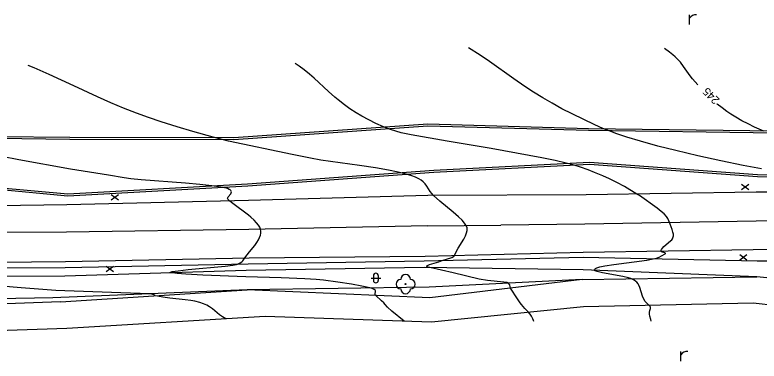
# Model space of a CAD drawing. Extents: x -593772 to -592667, y -1183541 to -1183371.
# Drawn here: x -592923.7 to -592846.1, y -1183541.5 to -1183505.4 of the extents above; entities that cross this region are included whole.
import ezdxf

# ---------------------------------------------------------------- set-up
doc = ezdxf.new("R2010")
doc.units = 0
for name, color, linetype in [('bez obruby', 7, 'Continuous'), ('hlavni vrstevnice', 7, 'Continuous'), ('popis ploch', 7, 'Continuous'), ('rozhrani ploch', 7, 'Continuous'), ('svisle dopravni znaceni', 7, 'Continuous'), ('terenni hrany', 7, 'Continuous'), ('vodorovne dopravni znaceni', 7, 'Continuous'), ('vrstevnice', 7, 'Continuous'), ('zelen', 7, 'Continuous')]:
    doc.layers.add(name, color=color, linetype=linetype)

msp = doc.modelspace()

# ---------------------------------------------------------------- linework, layer by layer
at = {"layer": 'bez obruby'}
for p, q in [((-592880.6, -1183524.23), (-592899.31, -1183524.75)), ((-592864.09, -1183524.15), (-592880.6, -1183524.23)), ((-592846.36, -1183523.87), (-592864.09, -1183524.15)), ((-592829.77, -1183523.8), (-592846.36, -1183523.87)), ((-592899.31, -1183524.75), (-592918.25, -1183525.18)), ((-592918.25, -1183525.18), (-592936.03, -1183525.44)), ((-592829.73, -1183529.64), (-592846.7, -1183529.89)), ((-592880.9, -1183530.57), (-592899.23, -1183530.75)), ((-592864.41, -1183530.16), (-592880.9, -1183530.57)), ((-592846.7, -1183529.89), (-592864.41, -1183530.16)), ((-592918.4, -1183531.12), (-592935.82, -1183531.3)), ((-592899.23, -1183530.75), (-592918.4, -1183531.12))]:
    msp.add_line(p, q, dxfattribs=at)
at = {"layer": 'hlavni vrstevnice'}
for points in [[(-592852.443, -1183512.671), (-592853.013, -1183512.029), (-592853.258, -1183511.72), (-592853.941, -1183510.749), (-592854.277, -1183510.319), (-592854.546, -1183510.018), (-592854.802, -1183509.762), (-592855.068, -1183509.524), (-592855.422, -1183509.244), (-592855.932, -1183508.889)], [(-592845.577, -1183517.486), (-592846.527, -1183517.076), (-592847.221, -1183516.746), (-592847.868, -1183516.408), (-592848.487, -1183516.054), (-592849.002, -1183515.733), (-592849.424, -1183515.451), (-592849.931, -1183515.08), (-592850.433, -1183514.679), (-592850.446, -1183514.668)], [(-592901.692, -1183537.077), (-592902.039, -1183536.871), (-592902.341, -1183536.655), (-592903.078, -1183536.043), (-592903.383, -1183535.831), (-592903.674, -1183535.666), (-592904.017, -1183535.507), (-592904.404, -1183535.365), (-592904.903, -1183535.226), (-592905.34, -1183535.149), (-592905.926, -1183535.082), (-592907.518, -1183534.928), (-592908.263, -1183534.829), (-592908.8, -1183534.726), (-592909.032, -1183534.664), (-592909.098, -1183534.629), (-592909.172, -1183534.563), (-592909.298, -1183534.524), (-592909.619, -1183534.487), (-592912.638, -1183534.364), (-592918.473, -1183534.167), (-592919.418, -1183534.12), (-592923.011, -1183533.839), (-592927.175, -1183533.483)]]:
    msp.add_lwpolyline(points, dxfattribs=at)
at = {"layer": 'popis ploch'}
for p, q in [((-592853.33, -1183506.38), (-592853.33, -1183505.38)), ((-592886.53, -1183532.82), (-592885.53, -1183532.82)), ((-592886.28, -1183532.57), (-592886.28, -1183533.07)), ((-592885.78, -1183532.57), (-592885.78, -1183533.07)), ((-592854.24, -1183541.49), (-592854.24, -1183540.49))]:
    msp.add_line(p, q, dxfattribs=at)
for centre, radius, start, end in [((-592852.693, -1183506.117), 0.746, 81.32683, 148.70696), ((-592886.031, -1183532.57), 0.25, 0, 180), ((-592886.031, -1183533.07), 0.25, 180, 0), ((-592853.603, -1183541.228), 0.746, 81.32683, 148.70696)]:
    msp.add_arc(centre, radius, start, end, dxfattribs=at)
at = {"layer": 'rozhrani ploch'}
for p, q in [((-592864.53, -1183532.96), (-592880.42, -1183534.89)), ((-592918.93, -1183535.32), (-592899.45, -1183534.04)), ((-592880.42, -1183534.89), (-592899.45, -1183534.04)), ((-592918.93, -1183535.32), (-592936.14, -1183535.94)), ((-592864.36, -1183535.82), (-592880.22, -1183537.41)), ((-592846.7, -1183535.46), (-592864.36, -1183535.82)), ((-592830.25, -1183537.2), (-592846.7, -1183535.46)), ((-592897.56, -1183536.83), (-592918.27, -1183538.07)), ((-592880.22, -1183537.41), (-592897.56, -1183536.83)), ((-592918.27, -1183538.07), (-592936.46, -1183538.75))]:
    msp.add_line(p, q, dxfattribs=at)
at = {"layer": 'svisle dopravni znaceni'}
for p, q in [((-592847.895, -1183523.591), (-592847.145, -1183523.029)), ((-592847.895, -1183523.029), (-592847.145, -1183523.591)), ((-592913.635, -1183524.681), (-592912.885, -1183524.119)), ((-592913.635, -1183524.119), (-592912.885, -1183524.681)), ((-592848.085, -1183530.931), (-592847.335, -1183530.369)), ((-592848.085, -1183530.369), (-592847.335, -1183530.931)), ((-592914.145, -1183532.131), (-592913.395, -1183531.569)), ((-592914.145, -1183531.569), (-592913.395, -1183532.131))]:
    msp.add_line(p, q, dxfattribs=at)
at = {"layer": 'terenni hrany'}
for p, q in [((-592900.86, -1183518.18), (-592880.6, -1183516.75)), ((-592880.6, -1183516.75), (-592863.86, -1183517.21)), ((-592863.86, -1183517.21), (-592843.44, -1183517.49)), ((-592934.32, -1183517.95), (-592917.94, -1183518.13)), ((-592917.94, -1183518.13), (-592900.86, -1183518.18)), ((-592863.75, -1183520.98), (-592879.99, -1183521.8)), ((-592846.23, -1183522.25), (-592863.75, -1183520.98)), ((-592879.99, -1183521.8), (-592899.4, -1183523.24)), ((-592918.15, -1183524.28), (-592935.47, -1183522.68)), ((-592829.92, -1183522.84), (-592846.23, -1183522.25)), ((-592899.4, -1183523.24), (-592918.15, -1183524.28)), ((-592899.36, -1183531.38), (-592918.42, -1183531.76)), ((-592880.99, -1183531.05), (-592899.36, -1183531.38)), ((-592864.41, -1183530.67), (-592880.99, -1183531.05)), ((-592846.26, -1183531.07), (-592864.41, -1183530.67)), ((-592829.79, -1183530.96), (-592846.26, -1183531.07)), ((-592918.42, -1183531.76), (-592935.94, -1183531.82)), ((-592899.55, -1183532.02), (-592918.48, -1183532.63)), ((-592881, -1183531.74), (-592899.55, -1183532.02)), ((-592864.41, -1183531.95), (-592881, -1183531.74)), ((-592846.3, -1183532.7), (-592864.41, -1183531.95)), ((-592918.48, -1183532.63), (-592935.99, -1183532.7)), ((-592864.53, -1183532.96), (-592846.3, -1183532.7)), ((-592829.97, -1183534.36), (-592846.3, -1183532.7)), ((-592864.53, -1183532.96), (-592880.48, -1183533.78)), ((-592899.45, -1183534.04), (-592919.72, -1183534.9)), ((-592880.48, -1183533.78), (-592899.45, -1183534.04)), ((-592919.72, -1183534.9), (-592936.16, -1183535.15))]:
    msp.add_line(p, q, dxfattribs=at)
at = {"layer": 'vodorovne dopravni znaceni'}
for p, q in [((-592829.67, -1183526.67), (-592846.37, -1183526.9)), ((-592880.66, -1183527.39), (-592899.28, -1183527.75)), ((-592880.66, -1183527.39), (-592873.015, -1183527.311)), ((-592864.23, -1183527.22), (-592873.015, -1183527.311)), ((-592846.37, -1183526.9), (-592864.23, -1183527.22)), ((-592918.29, -1183528.04), (-592936.08, -1183528.16)), ((-592899.28, -1183527.75), (-592918.29, -1183528.04))]:
    msp.add_line(p, q, dxfattribs=at)
at = {"layer": 'vrstevnice'}
for points in [[(-592845.829, -1183521.431), (-592847.71, -1183521.077), (-592850.065, -1183520.598), (-592852.448, -1183520.075), (-592854.734, -1183519.534), (-592856.63, -1183519.052), (-592858.434, -1183518.555), (-592859.845, -1183518.128), (-592860.915, -1183517.773), (-592861.708, -1183517.482), (-592862.378, -1183517.212), (-592863.181, -1183516.857), (-592865.558, -1183515.705), (-592866.622, -1183515.158), (-592867.646, -1183514.598), (-592868.635, -1183514.023), (-592869.592, -1183513.432), (-592870.483, -1183512.848), (-592871.629, -1183512.057), (-592874.188, -1183510.234), (-592875.143, -1183509.586), (-592876.377, -1183508.801)], [(-592869.554, -1183537.365), (-592869.579, -1183537.255), (-592869.652, -1183537.077), (-592869.808, -1183536.799), (-592869.956, -1183536.583), (-592870.149, -1183536.366), (-592870.511, -1183535.988), (-592870.856, -1183535.578), (-592870.984, -1183535.408), (-592871.271, -1183534.984), (-592871.974, -1183533.863), (-592872.019, -1183533.755), (-592872.064, -1183533.536), (-592872.113, -1183533.448), (-592872.201, -1183533.362), (-592872.348, -1183533.306), (-592872.68, -1183533.25), (-592874.378, -1183533.093), (-592875.253, -1183532.928), (-592877.962, -1183532.273), (-592880.403, -1183531.737), (-592880.619, -1183531.672), (-592880.7, -1183531.623), (-592880.719, -1183531.588), (-592880.71, -1183531.554), (-592880.641, -1183531.499), (-592880.454, -1183531.42), (-592879.476, -1183531.135), (-592879.131, -1183531.002), (-592878.116, -1183530.674), (-592877.919, -1183530.584), (-592877.866, -1183530.533), (-592877.699, -1183530.162), (-592877.44, -1183529.703), (-592876.873, -1183528.782), (-592876.687, -1183528.424), (-592876.564, -1183528.112), (-592876.511, -1183527.868), (-592876.506, -1183527.72), (-592876.527, -1183527.572), (-592876.581, -1183527.418), (-592876.639, -1183527.311), (-592876.788, -1183527.097), (-592877.041, -1183526.802), (-592877.4, -1183526.448), (-592877.984, -1183525.938), (-592879.35, -1183524.808), (-592880.015, -1183524.205), (-592880.198, -1183524.013), (-592880.364, -1183523.791), (-592880.706, -1183523.223), (-592880.888, -1183522.982), (-592881.085, -1183522.784), (-592881.292, -1183522.624), (-592881.557, -1183522.463), (-592881.898, -1183522.302), (-592882.291, -1183522.154), (-592882.881, -1183521.982), (-592883.718, -1183521.779), (-592884.715, -1183521.572), (-592886.055, -1183521.332), (-592887.755, -1183521.071), (-592891.756, -1183520.516), (-592892.847, -1183520.325), (-592894.773, -1183519.933), (-592901.397, -1183518.553), (-592902.982, -1183518.134), (-592905.109, -1183517.536), (-592906.754, -1183517.047), (-592908.418, -1183516.52), (-592909.745, -1183516.07), (-592911.012, -1183515.608), (-592912.35, -1183515.086), (-592913.665, -1183514.536), (-592915.066, -1183513.909), (-592917.53, -1183512.758), (-592920.1, -1183511.586), (-592921.674, -1183510.899), (-592922.284, -1183510.641)], [(-592857.327, -1183537.314), (-592857.359, -1183537.153), (-592857.474, -1183536.787), (-592857.504, -1183536.588), (-592857.499, -1183536.398), (-592857.461, -1183536.222), (-592857.381, -1183536.009), (-592857.373, -1183535.939), (-592857.389, -1183535.868), (-592857.433, -1183535.794), (-592857.778, -1183535.454), (-592857.937, -1183535.254), (-592858.085, -1183535.01), (-592858.214, -1183534.718), (-592858.494, -1183533.799), (-592858.595, -1183533.563), (-592858.687, -1183533.415), (-592858.813, -1183533.271), (-592858.925, -1183533.17), (-592859.078, -1183533.061), (-592859.426, -1183532.876), (-592859.701, -1183532.789), (-592860.279, -1183532.663), (-592862.397, -1183532.279), (-592862.935, -1183532.154), (-592863.144, -1183532.084), (-592863.238, -1183532.033), (-592863.259, -1183531.999), (-592863.226, -1183531.918), (-592863.207, -1183531.891), (-592863.12, -1183531.827), (-592862.97, -1183531.759), (-592862.673, -1183531.668), (-592862.155, -1183531.554), (-592861.221, -1183531.4), (-592857.768, -1183530.942), (-592857.111, -1183530.829), (-592856.769, -1183530.745), (-592856.489, -1183530.645), (-592856.258, -1183530.523), (-592855.859, -1183530.289), (-592855.83, -1183530.263), (-592855.835, -1183530.237), (-592855.905, -1183530.197), (-592856.244, -1183530.08), (-592856.29, -1183530.038), (-592856.276, -1183529.927), (-592856.238, -1183529.831), (-592856.149, -1183529.7), (-592856.012, -1183529.55), (-592855.297, -1183528.959), (-592855.163, -1183528.823), (-592855.093, -1183528.729), (-592855.045, -1183528.633), (-592855.003, -1183528.435), (-592855.007, -1183528.234), (-592855.045, -1183528.03), (-592855.127, -1183527.775), (-592855.355, -1183527.209), (-592855.476, -1183526.842), (-592855.587, -1183526.628), (-592855.737, -1183526.411), (-592855.972, -1183526.141), (-592856.263, -1183525.867), (-592856.692, -1183525.525), (-592858.543, -1183524.229), (-592858.807, -1183524.063), (-592860.113, -1183523.28), (-592860.905, -1183522.844), (-592861.654, -1183522.472), (-592862.355, -1183522.157), (-592863.219, -1183521.804), (-592863.893, -1183521.547), (-592864.691, -1183521.26), (-592865.338, -1183521.057), (-592866.185, -1183520.828), (-592867.342, -1183520.559), (-592868.726, -1183520.278), (-592874.001, -1183519.32), (-592878.585, -1183518.554), (-592882.339, -1183517.891), (-592883.403, -1183517.665), (-592883.95, -1183517.515), (-592884.521, -1183517.324), (-592885.247, -1183517.041), (-592886.033, -1183516.694), (-592886.775, -1183516.333), (-592887.509, -1183515.938), (-592888.079, -1183515.601), (-592888.731, -1183515.178), (-592889.309, -1183514.766), (-592889.979, -1183514.24), (-592890.312, -1183513.961), (-592890.971, -1183513.374), (-592892.458, -1183511.986), (-592892.964, -1183511.54), (-592893.525, -1183511.087), (-592894.042, -1183510.714), (-592894.454, -1183510.449)], [(-592883.072, -1183537.315), (-592884.355, -1183536.267), (-592884.805, -1183535.861), (-592885.077, -1183535.579), (-592885.215, -1183535.414), (-592885.428, -1183535.184), (-592886.037, -1183534.636), (-592886.094, -1183534.562), (-592886.112, -1183534.487), (-592886.06, -1183534.229), (-592886.071, -1183534.155), (-592886.119, -1183534.081), (-592886.222, -1183534.005), (-592886.403, -1183533.928), (-592886.647, -1183533.857), (-592887.487, -1183533.671), (-592888.563, -1183533.471), (-592889.981, -1183533.247), (-592891.491, -1183533.045), (-592892.261, -1183532.973), (-592893.429, -1183532.902), (-592895.912, -1183532.804), (-592899.609, -1183532.683), (-592904.094, -1183532.514), (-592905.842, -1183532.424), (-592906.756, -1183532.353), (-592907.259, -1183532.293), (-592907.42, -1183532.266), (-592907.488, -1183532.238), (-592907.492, -1183532.224), (-592907.443, -1183532.194), (-592907.274, -1183532.15), (-592906.654, -1183532.055), (-592905.608, -1183531.932), (-592901.735, -1183531.57), (-592900.932, -1183531.471), (-592900.557, -1183531.395), (-592900.455, -1183531.362), (-592900.176, -1183531.246), (-592900.005, -1183531.141), (-592899.896, -1183531.035), (-592899.701, -1183530.723), (-592899.207, -1183530.1), (-592898.671, -1183529.442), (-592898.436, -1183529.111), (-592898.266, -1183528.823), (-592898.154, -1183528.579), (-592898.076, -1183528.336), (-592898.042, -1183528.139), (-592898.038, -1183527.939), (-592898.07, -1183527.724), (-592898.148, -1183527.519), (-592898.268, -1183527.311), (-592898.466, -1183527.051), (-592898.716, -1183526.786), (-592899.072, -1183526.465), (-592899.314, -1183526.267), (-592900.932, -1183525.055), (-592901.253, -1183524.793), (-592901.4, -1183524.682), (-592901.464, -1183524.606), (-592901.489, -1183524.531), (-592901.482, -1183524.456), (-592901.434, -1183524.354), (-592901.173, -1183524.023), (-592901.121, -1183523.921), (-592901.104, -1183523.845), (-592901.116, -1183523.77), (-592901.158, -1183523.695), (-592901.235, -1183523.626), (-592901.325, -1183523.573), (-592901.513, -1183523.498), (-592901.946, -1183523.393), (-592903.132, -1183523.213), (-592904.377, -1183523.064), (-592905.899, -1183522.919), (-592910.508, -1183522.566), (-592911.573, -1183522.46), (-592912.288, -1183522.361), (-592913.899, -1183522.076), (-592917.895, -1183521.475), (-592923.272, -1183520.495), (-592926.856, -1183519.81)]]:
    msp.add_lwpolyline(points, dxfattribs=at)
at = {"layer": 'zelen'}
for p, q in [((-592900.853, -1183518.38), (-592880.596, -1183516.95)), ((-592880.596, -1183516.95), (-592863.864, -1183517.41)), ((-592863.864, -1183517.41), (-592843.439, -1183517.69)), ((-592934.321, -1183518.15), (-592917.941, -1183518.33)), ((-592917.941, -1183518.33), (-592900.853, -1183518.38)), ((-592863.748, -1183520.78), (-592880.002, -1183521.6)), ((-592846.219, -1183522.05), (-592863.748, -1183520.78)), ((-592880.002, -1183521.6), (-592899.415, -1183523.041)), ((-592829.918, -1183522.64), (-592846.219, -1183522.05)), ((-592918.146, -1183524.079), (-592935.454, -1183522.481)), ((-592899.411, -1183523.04), (-592918.146, -1183524.079))]:
    msp.add_line(p, q, dxfattribs=at)
msp.add_circle((-592882.93, -1183533.46), 0.05, dxfattribs=at)
for centre, start, end in [((-592882.93, -1183532.96), 0, 180), ((-592883.43, -1183533.46), 90, 270), ((-592882.43, -1183533.46), 270, 90), ((-592882.93, -1183533.96), 180, 0)]:
    msp.add_arc(centre, 0.5, start, end, dxfattribs=at)

# ---------------------------------------------------------------- texts
at = {"layer": 'hlavni vrstevnice'}
msp.add_text('245', height=0.8351, rotation=134.98728, dxfattribs=at).set_placement((-592850.13, -1183514.192))

doc.saveas('drawing.dxf')
